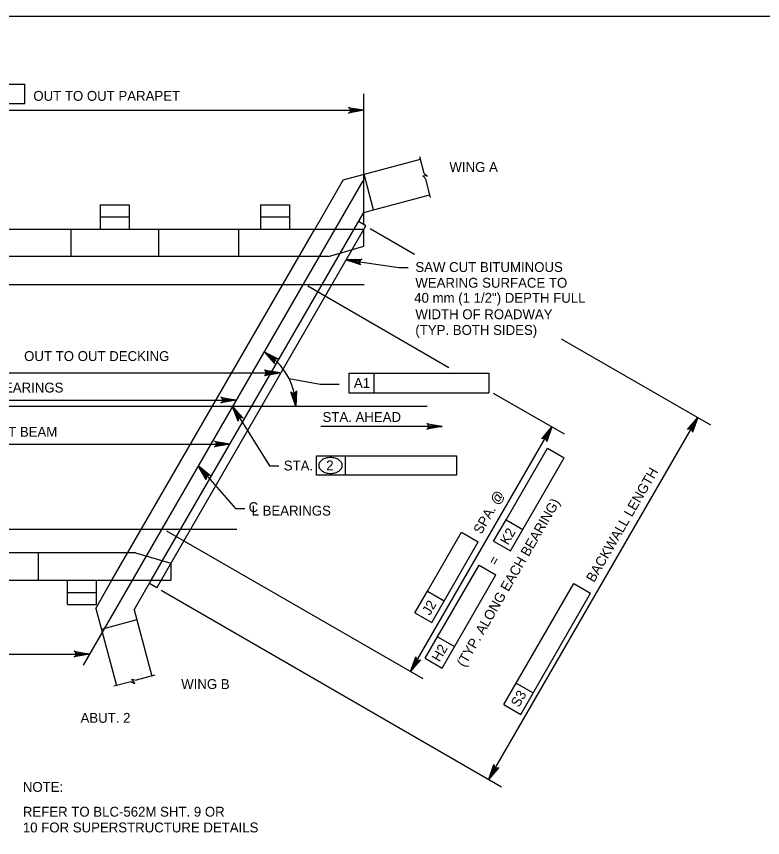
# Model space of a CAD drawing. Extents: x -13 to 81, y -176 to 0.
# Drawn here: x 13.06 to 22.13, y -120.73 to -110.75 of the extents above; entities that cross this region are included whole.
import ezdxf

# ---------------------------------------------------------------- set-up
doc = ezdxf.new("R2010")
doc.units = 0
for name, color, linetype in [('Level 1', 7, 'Continuous'), ('Level 2', 7, 'Continuous'), ('Level 3', 7, 'Continuous'), ('Level 4', 7, 'Continuous')]:
    doc.layers.add(name, color=color, linetype=linetype)

# ---------------------------------------------------------------- blocks, each defined once
blk = doc.blocks.new('AR')
at = {"layer": 'Level 4'}
blk.add_lwpolyline([(3.33, 0.56), (3.33, -0.56), (0, 0)], close=True, dxfattribs=at)

msp = doc.modelspace()

# ---------------------------------------------------------------- linework, layer by layer
at = {"layer": 'Level 1'}
msp.add_lwpolyline([(1.75, -131.25), (33.25, -131.25), (33.25, -110.75), (1.75, -110.75)], close=True, dxfattribs=at)
at = {"layer": 'Level 2'}
for p, q in [((17.0344, -112.7358), (17.9716, -112.4847)), ((17.0344, -112.7358), (16.6892, -113.3337)), ((17.4041, -113.0996), (17.2884, -112.6678)), ((17.4041, -113.0996), (18.0873, -112.9165)), ((14.0799, -113.0385), (14.0799, -113.3337)), ((14.0799, -113.0385), (14.4342, -113.0385)), ((14.4342, -113.0385), (14.4342, -113.3337)), ((16.0287, -113.0385), (16.0287, -113.3337)), ((16.0287, -113.0385), (16.3831, -113.0385)), ((16.3831, -113.0385), (16.3831, -113.3337)), ((17.1666, -113.3337), (17.2831, -113.132)), ((17.2831, -113.132), (17.4041, -113.0996)), ((17.308, -113.2956), (17.2185, -113.2439)), ((9.1005, -113.3337), (17.2858, -113.3337)), ((14.2245, -117.6028), (16.6892, -113.3337)), ((14.7018, -117.6028), (17.1666, -113.3337)), ((14.7693, -117.6927), (17.308, -113.2956)), ((17.2858, -113.5404), (17.2858, -113.3337)), ((16.8567, -113.6659), (17.2858, -113.5404)), ((16.8567, -113.6659), (9.5297, -113.6659)), ((14.5113, -117.2706), (7.1842, -117.2706)), ((14.5113, -117.2706), (14.9405, -117.3961)), ((14.9405, -117.3961), (14.9405, -117.6028)), ((6.755, -117.6028), (14.9405, -117.6028)), ((13.6833, -117.8981), (13.6833, -117.6028)), ((14.0272, -117.9446), (14.2245, -117.6028)), ((14.0377, -117.8981), (14.0377, -117.6028)), ((14.4946, -117.9618), (14.7018, -117.6028)), ((14.7693, -117.6927), (14.6798, -117.641)), ((13.6833, -117.8981), (14.0377, -117.8981)), ((14.0272, -117.9446), (14.2782, -118.8817)), ((14.4946, -117.9618), (14.527, -118.0828)), ((14.527, -118.0828), (14.0953, -118.1986)), ((14.527, -118.0828), (14.71, -118.766))]:
    msp.add_line(p, q, dxfattribs=at)
at = {"layer": 'Level 3'}
for p, q in [((18.0183, -112.6592), (17.9634, -112.4543)), ((18.0183, -112.6592), (18.0603, -112.6906)), ((18.0603, -112.6906), (18.0006, -112.687)), ((18.0006, -112.687), (18.0362, -112.7259)), ((18.0962, -112.9499), (18.0362, -112.7259)), ((14.0799, -113.1861), (14.4342, -113.1861)), ((16.0287, -113.1861), (16.3831, -113.1861)), ((13.7248, -113.3337), (13.7248, -113.6659)), ((14.7886, -113.3337), (14.7886, -113.6659)), ((15.763, -113.3337), (15.763, -113.6659)), ((13.329, -117.2706), (13.329, -117.6028)), ((13.6833, -117.7504), (14.0377, -117.7504)), ((14.4527, -118.835), (14.2477, -118.8899)), ((14.4527, -118.835), (14.5009, -118.8557)), ((14.4679, -118.8057), (14.5194, -118.8171)), ((14.5009, -118.8557), (14.4679, -118.8057)), ((14.7434, -118.7571), (14.5194, -118.8171))]:
    msp.add_line(p, q, dxfattribs=at)
at = {"layer": 'Level 4'}
for p, q in [((11.7684, -111.574), (13.1668, -111.574)), ((13.1665, -111.8102), (13.1668, -111.574)), ((17.2858, -113.2754), (17.2858, -111.6915)), ((11.4657, -111.8102), (13.1665, -111.8102)), ((9.1005, -111.8908), (17.2858, -111.8908)), ((17.2725, -112.7492), (13.8753, -118.6332)), ((17.3621, -113.3268), (17.902, -113.6385)), ((17.0702, -113.7076), (17.7106, -113.8001)), ((17.7106, -113.8001), (17.824, -113.8001)), ((17.2902, -114.0119), (3.3682, -114.0119)), ((16.6039, -114.0252), (18.3184, -115.0152)), ((19.6824, -114.6664), (21.4967, -115.7139)), ((8.2122, -115.0812), (16.2637, -115.0812)), ((16.3758, -115.1506), (16.7534, -115.2187)), ((17.1032, -115.0862), (17.4057, -115.0862)), ((17.1032, -115.0862), (17.1032, -115.3224)), ((17.4057, -115.0862), (17.4057, -115.3224)), ((17.4057, -115.0862), (18.804, -115.0862)), ((18.804, -115.0862), (18.804, -115.3224)), ((16.7534, -115.2187), (16.9833, -115.2187)), ((17.1032, -115.3224), (18.804, -115.3224)), ((18.8572, -115.3263), (19.7169, -115.8226)), ((8.3848, -115.4123), (15.7349, -115.4123)), ((18.0531, -115.4909), (6.3614, -115.4909)), ((15.6895, -115.4909), (16.1367, -116.2128)), ((18.8022, -120.0211), (21.3409, -115.6239)), ((18.2354, -115.7317), (16.7626, -115.7317)), ((17.8525, -118.7117), (19.5697, -115.7376)), ((7.8564, -115.9462), (15.6583, -115.9462)), ((19.0128, -116.8657), (19.5153, -115.9952)), ((19.5153, -115.9952), (19.7199, -116.1132)), ((16.7107, -116.3247), (16.7107, -116.0886)), ((16.7107, -116.0886), (17.0605, -116.0886)), ((17.0605, -116.3247), (17.0605, -116.0886)), ((17.0605, -116.0886), (18.4114, -116.0886)), ((18.4114, -116.0886), (18.4114, -116.3247)), ((19.0662, -117.2457), (19.7199, -116.1132)), ((15.2725, -116.2132), (15.7264, -116.7283)), ((16.1367, -116.2128), (16.2501, -116.2128)), ((18.4114, -116.3247), (16.7107, -116.3247)), ((15.7264, -116.7283), (15.8397, -116.7283)), ((18.8616, -117.1276), (19.0128, -116.8657)), ((19.0128, -116.8657), (19.2173, -116.9838)), ((15.74, -116.9861), (3.3495, -116.9861)), ((14.8867, -116.9994), (17.9998, -118.7968)), ((18.0573, -117.7344), (18.4705, -117.0187)), ((18.4705, -117.0187), (18.6751, -117.1368)), ((18.1107, -118.1144), (18.6751, -117.1368)), ((18.8616, -117.1276), (19.0662, -117.2457)), ((18.1815, -118.2881), (18.6841, -117.4177)), ((18.6841, -117.4177), (18.8887, -117.5357)), ((18.2348, -118.6682), (18.8887, -117.5357)), ((19.137, -118.8513), (19.8362, -117.6403)), ((19.8362, -117.6403), (20.0407, -117.7585)), ((14.8234, -117.7239), (18.9581, -120.1111)), ((17.9061, -117.9963), (18.0573, -117.7344)), ((18.0573, -117.7344), (18.2619, -117.8525)), ((19.1903, -119.2314), (20.0407, -117.7585)), ((17.9061, -117.9963), (18.1107, -118.1144)), ((18.0303, -118.5501), (18.1815, -118.2881)), ((18.1815, -118.2881), (18.3861, -118.4062)), ((6.6027, -118.499), (13.9528, -118.499)), ((18.0303, -118.5501), (18.2348, -118.6682)), ((18.9857, -119.1133), (19.137, -118.8513)), ((19.137, -118.8513), (19.3416, -118.9695)), ((18.9857, -119.1133), (19.1903, -119.2314))]:
    msp.add_line(p, q, dxfattribs=at)
for points in [[(17.2858, -111.8908), (17.0994, -111.9257), (17.1137, -111.9158), (17.1212, -111.9033), (17.1233, -111.8908), (17.1212, -111.8783), (17.1137, -111.8658), (17.0994, -111.8559), (17.2858, -111.8908), (17.1137, -111.8658), (17.1212, -111.8783), (17.2858, -111.8908), (17.1233, -111.8908), (17.1212, -111.9033), (17.2858, -111.8908), (17.1137, -111.9158)], [(17.0702, -113.7076), (17.2597, -113.6997), (17.244, -113.7074), (17.2349, -113.7188), (17.231, -113.7308), (17.2313, -113.7435), (17.2369, -113.7569), (17.2497, -113.7688), (17.0702, -113.7076), (17.2369, -113.7569), (17.2313, -113.7435), (17.0702, -113.7076), (17.231, -113.7308), (17.2349, -113.7188), (17.0702, -113.7076), (17.244, -113.7074)], [(16.0729, -114.827), (16.2427, -114.9117), (16.2252, -114.9109), (16.2117, -114.9164), (16.2025, -114.9251), (16.1967, -114.9363), (16.195, -114.9507), (16.2004, -114.9673), (16.0729, -114.827), (16.195, -114.9507), (16.1967, -114.9363), (16.0729, -114.827), (16.2025, -114.9251), (16.2117, -114.9164), (16.0729, -114.827), (16.2252, -114.9109)], [(16.2637, -115.0812), (16.0773, -115.1161), (16.0917, -115.1062), (16.0991, -115.0937), (16.1013, -115.0812), (16.0991, -115.0687), (16.0917, -115.0562), (16.0773, -115.0463), (16.2637, -115.0812), (16.0917, -115.0562), (16.0991, -115.0687), (16.2637, -115.0812), (16.1013, -115.0812), (16.0991, -115.0937), (16.2637, -115.0812), (16.0917, -115.1062)], [(16.4567, -115.4908), (16.3982, -115.3104), (16.4098, -115.3234), (16.4232, -115.3292), (16.4359, -115.3297), (16.448, -115.3259), (16.4594, -115.317), (16.4675, -115.3015), (16.4567, -115.4908), (16.4594, -115.317), (16.448, -115.3259), (16.4567, -115.4908), (16.4359, -115.3297), (16.4232, -115.3292), (16.4567, -115.4908), (16.4098, -115.3234)], [(15.7349, -115.4123), (15.5485, -115.4472), (15.5628, -115.4373), (15.5702, -115.4248), (15.5724, -115.4123), (15.5702, -115.3998), (15.5628, -115.3873), (15.5485, -115.3774), (15.7349, -115.4123), (15.5628, -115.3873), (15.5702, -115.3998), (15.7349, -115.4123), (15.5724, -115.4123), (15.5702, -115.4248), (15.7349, -115.4123), (15.5628, -115.4373)], [(15.6895, -115.4909), (15.8174, -115.631), (15.8013, -115.624), (15.7868, -115.6243), (15.7751, -115.6291), (15.7656, -115.6375), (15.7588, -115.6503), (15.7579, -115.6678), (15.6895, -115.4909), (15.7588, -115.6503), (15.7656, -115.6375), (15.6895, -115.4909), (15.7751, -115.6291), (15.7868, -115.6243), (15.6895, -115.4909), (15.8013, -115.624)], [(21.3409, -115.6239), (21.278, -115.8028), (21.2765, -115.7854), (21.2694, -115.7728), (21.2597, -115.7647), (21.2477, -115.7602), (21.2332, -115.7604), (21.2174, -115.7679), (21.3409, -115.6239), (21.2332, -115.7604), (21.2477, -115.7602), (21.3409, -115.6239), (21.2597, -115.7647), (21.2694, -115.7728), (21.3409, -115.6239), (21.2765, -115.7854)], [(18.2354, -115.7317), (18.049, -115.7667), (18.0633, -115.7567), (18.0708, -115.7442), (18.0729, -115.7317), (18.0708, -115.7193), (18.0633, -115.7067), (18.049, -115.6968), (18.2354, -115.7317), (18.0633, -115.7067), (18.0708, -115.7193), (18.2354, -115.7317), (18.0729, -115.7317), (18.0708, -115.7442), (18.2354, -115.7317), (18.0633, -115.7567)], [(19.5697, -115.7376), (19.5068, -115.9165), (19.5053, -115.8991), (19.4982, -115.8864), (19.4884, -115.8783), (19.4765, -115.8739), (19.462, -115.8741), (19.4462, -115.8816), (19.5697, -115.7376), (19.462, -115.8741), (19.4765, -115.8739), (19.5697, -115.7376), (19.4884, -115.8783), (19.4982, -115.8864), (19.5697, -115.7376), (19.5053, -115.8991)], [(15.6583, -115.9462), (15.4719, -115.9811), (15.4863, -115.9712), (15.4937, -115.9587), (15.4958, -115.9462), (15.4937, -115.9337), (15.4863, -115.9212), (15.4719, -115.9112), (15.6583, -115.9462), (15.4863, -115.9212), (15.4937, -115.9337), (15.6583, -115.9462), (15.4958, -115.9462), (15.4937, -115.9587), (15.6583, -115.9462), (15.4863, -115.9712)], [(15.2725, -116.2132), (15.422, -116.3299), (15.405, -116.3257), (15.3907, -116.3284), (15.3799, -116.3351), (15.372, -116.3449), (15.3675, -116.3588), (15.3695, -116.3762), (15.2725, -116.2132), (15.3675, -116.3588), (15.372, -116.3449), (15.2725, -116.2132), (15.3799, -116.3351), (15.3907, -116.3284), (15.2725, -116.2132), (15.405, -116.3257)], [(13.9528, -118.499), (13.7664, -118.5339), (13.7807, -118.524), (13.7882, -118.5115), (13.7903, -118.499), (13.7882, -118.4865), (13.7807, -118.474), (13.7664, -118.4641), (13.9528, -118.499), (13.7807, -118.474), (13.7882, -118.4865), (13.9528, -118.499), (13.7903, -118.499), (13.7882, -118.5115), (13.9528, -118.499), (13.7807, -118.524)], [(17.8525, -118.7117), (17.9154, -118.5327), (17.9169, -118.5502), (17.924, -118.5628), (17.9337, -118.5709), (17.9457, -118.5753), (17.9602, -118.5752), (17.976, -118.5677), (17.8525, -118.7117), (17.9602, -118.5752), (17.9457, -118.5753), (17.8525, -118.7117), (17.9337, -118.5709), (17.924, -118.5628), (17.8525, -118.7117), (17.9169, -118.5502)], [(18.8022, -120.0211), (18.8651, -119.8422), (18.8666, -119.8596), (18.8737, -119.8722), (18.8834, -119.8803), (18.8953, -119.8847), (18.9098, -119.8846), (18.9257, -119.8771), (18.8022, -120.0211), (18.9098, -119.8846), (18.8953, -119.8847), (18.8022, -120.0211), (18.8834, -119.8803), (18.8737, -119.8722), (18.8022, -120.0211), (18.8666, -119.8596)]]:
    msp.add_lwpolyline(points, dxfattribs=at)
for points in [[(17.1742, -113.7417), (17.1795, -113.7043), (17.0646, -113.7068)], [(16.1503, -115.0622), (16.1503, -115.1001), (16.2637, -115.0812)], [(21.2636, -115.7179), (21.2982, -115.7379), (21.3409, -115.6239)], [(19.4966, -115.8263), (19.5293, -115.8452), (19.5697, -115.7376)], [(15.5177, -115.9273), (15.5177, -115.9651), (15.6312, -115.9462)], [(15.3325, -116.3098), (15.3608, -116.2848), (15.2717, -116.2122)], [(17.8928, -118.6041), (17.9256, -118.623), (17.8525, -118.7117)], [(18.8449, -119.9072), (18.8795, -119.9272), (18.8022, -120.0211)]]:
    msp.add_lwpolyline(points, close=True, dxfattribs=at)
for centre, radius, start, end in [((15.6895, -115.491), 0.7661, 359.99963, 59.99834), ((16.8403, -116.2295), 0.1099, 124.10897, 148.55069), ((16.8643, -116.265), 0.1526, 105.67084, 124.10897), ((16.88, -116.321), 0.2108, 90, 105.67084), ((16.88, -116.321), 0.2108, 74.32916, 90), ((16.8957, -116.265), 0.1526, 55.89103, 74.32916), ((16.9197, -116.2295), 0.1099, 31.44931, 55.89103), ((16.8038, -116.2072), 0.067, 148.55069, 180), ((16.8038, -116.2072), 0.067, 180, 211.44931), ((16.8403, -116.1848), 0.1099, 211.44931, 235.89103), ((16.9197, -116.1848), 0.1099, 304.10897, 328.55069), ((16.9562, -116.2072), 0.067, 0, 31.44931), ((16.9562, -116.2072), 0.067, 328.55069, 0), ((16.8643, -116.1494), 0.1526, 235.89103, 254.32916), ((16.88, -116.0934), 0.2108, 254.32916, 270), ((16.88, -116.0934), 0.2108, 270, 285.67084), ((16.8957, -116.1494), 0.1526, 285.67084, 304.10897)]:
    msp.add_arc(centre, radius, start, end, dxfattribs=at)

# ---------------------------------------------------------------- block references
at = {"layer": 'Level 4', "xscale": 0.035433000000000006, "yscale": 0.035433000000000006, "rotation": 180}
msp.add_blockref('AR', (13.9358, -118.499), dxfattribs=at)

# ---------------------------------------------------------------- texts
at = {"layer": 'Level 4'}
for s, p in [('OUT TO OUT PARAPET ', (13.2693, -111.7756)), ('WING A', (18.3248, -112.64)), ('SAW CUT BITUMINOUS', (17.9107, -113.8558)), ('WEARING SURFACE TO', (17.9107, -114.0469)), ('40 mm (1 1/2") DEPTH FULL', (17.8969, -114.2297)), ('WIDTH OF ROADWAY', (17.9107, -114.4294)), ('(TYP. BOTH SIDES)', (17.9107, -114.6206)), ('OUT TO OUT DECKING', (13.1572, -114.9376)), ('C/C BEARINGS', (12.4845, -115.3203)), ('STA. AHEAD', (16.7829, -115.6782)), ('OUT TO OUT BEAM', (12.0717, -115.8585)), ('STA.', (16.3122, -116.2677)), ('2', (16.828, -116.2654)), ('C', (15.885, -116.7736)), ('L BEARINGS', (15.9212, -116.816)), ('WING B', (15.0661, -118.9234)), ('ABUT. 2', (13.8427, -119.334)), ('NOTE:', (13.142, -120.1733)), ('REFER TO BLC-562M SHT. 9 OR', (13.142, -120.4749)), ('10 FOR SUPERSTRUCTURE DETAILS', (13.142, -120.6661))]:
    msp.add_text(s, height=0.12, dxfattribs=at).set_placement(p)
for s, rotation, p in [('A1', 359.93823, (17.1641, -115.2642)), ('BACKWALL LENGTH', 60, (20.0814, -117.637)), ('SPA. @', 60, (18.7114, -117.0522)), ('(TYP. ALONG EACH BEARING)', 60, (18.5102, -118.6667)), ('K2', 59.93823, (19.0358, -117.1819)), ('= ', 60, (18.8934, -117.4323)), ('J2', 59.93823, (18.0882, -118.0372)), ('H2', 59.93823, (18.2052, -118.6032)), ('S3', 59.93823, (19.1676, -119.1547))]:
    msp.add_text(s, height=0.12, rotation=rotation, dxfattribs=at).set_placement(p)

doc.saveas('drawing.dxf')
